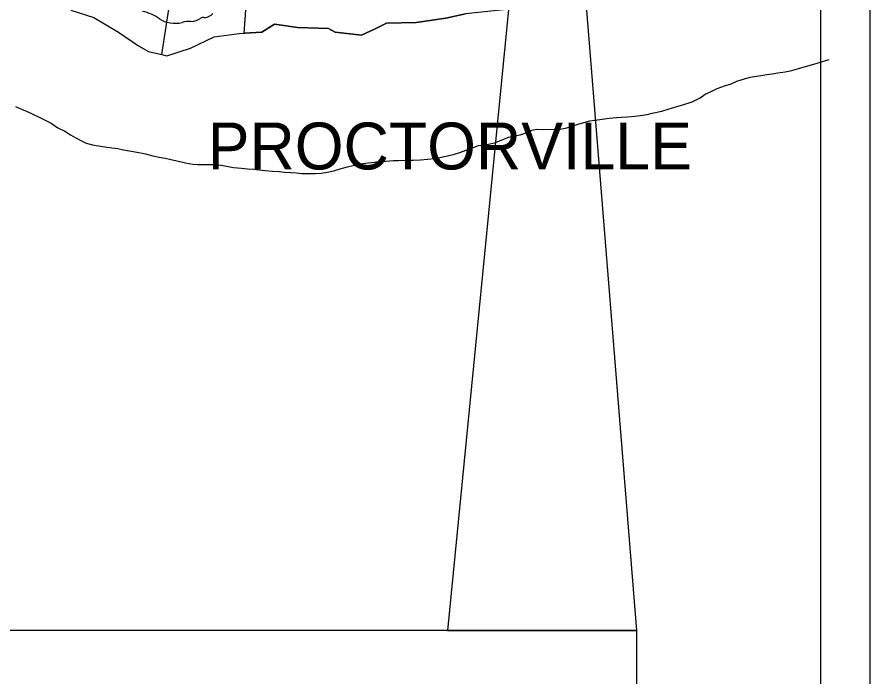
# Model space of a CAD drawing. Extents: x 0 to 34, y 0 to 22.
# Drawn here: x 7.778 to 9.5, y 15.102 to 16.434 of the extents above; entities that cross this region are included whole.
import ezdxf

# ---------------------------------------------------------------- set-up
doc = ezdxf.new("R2010")
doc.units = 0
for name, color, linetype in [('GM_X_Corporation', 7, 'Continuous'), ('GM_X_Corporation_Text', 7, 'Continuous'), ('GM_X_County', 7, 'Continuous'), ('GM_X_Major_River', 7, 'Continuous'), ('GM_X_State_Route', 7, 'Continuous'), ('GM_X_State_Shield', 7, 'Continuous'), ('GM_X_Township', 7, 'Continuous'), ('SH_Data', 7, 'Continuous'), ('SH_Text', 7, 'Continuous')]:
    doc.layers.add(name, color=color, linetype=linetype)

msp = doc.modelspace()

# ---------------------------------------------------------------- linework, layer by layer
at = {"layer": 'GM_X_Corporation'}
msp.add_lwpolyline([(8.236, 16.4015), (8.2709, 16.8756), (8.4678, 16.8002), (8.4665, 16.7841), (8.5125, 16.7805), (8.5113, 16.765), (8.6273, 16.756), (8.6258, 16.7367), (8.9074, 16.7147), (8.8957, 16.4847), (8.8556, 16.4772), (8.7669, 16.4493), (8.683, 16.4407), (8.6432, 16.4316), (8.5837, 16.4231), (8.5237, 16.4215), (8.501, 16.41), (8.4733, 16.3978), (8.4202, 16.4034), (8.4065, 16.411), (8.3439, 16.4128), (8.2972, 16.4195), (8.2722, 16.4039)], close=True, dxfattribs=at)
at = {"layer": 'GM_X_County'}
msp.add_lwpolyline([(7.8859, 16.4481), (7.9326, 16.4334), (7.9823, 16.4038), (8.023, 16.3761), (8.0428, 16.3644), (8.0701, 16.3583), (8.0803, 16.3561), (8.1277, 16.3713), (8.1755, 16.3942), (8.2259, 16.4008), (8.2722, 16.4039), (8.2972, 16.4195), (8.3439, 16.4128), (8.4065, 16.411), (8.4202, 16.4034), (8.4733, 16.3978), (8.501, 16.41), (8.5237, 16.4215), (8.5837, 16.4231), (8.6432, 16.4316), (8.683, 16.4407)], dxfattribs=at)
at = {"layer": 'GM_X_Major_River'}
for points in [[(9.0359, 16.2354), (9.0498, 16.2373), (9.06, 16.2401), (9.0797, 16.2439), (9.0925, 16.2478), (9.1102, 16.2532), (9.1219, 16.2567), (9.1412, 16.2629), (9.157, 16.2709), (9.1672, 16.2786), (9.1808, 16.2847), (9.1913, 16.2897), (9.2083, 16.2962), (9.2181, 16.2985), (9.2313, 16.3043), (9.2464, 16.3093), (9.2581, 16.3124), (9.2797, 16.3159), (9.2917, 16.3179), (9.3027, 16.3191), (9.3137, 16.3214), (9.3288, 16.3234), (9.342, 16.3265), (9.3601, 16.3315), (9.3771, 16.3365), (9.3937, 16.3412), (9.4111, 16.3466), (9.4175, 16.3484)], [(7.7746, 16.2538), (7.7863, 16.2481), (7.7981, 16.2432), (7.8079, 16.2387), (7.8239, 16.2315), (7.8345, 16.2262), (7.8466, 16.2198), (7.8603, 16.2107), (7.8739, 16.2039), (7.8857, 16.1963), (7.8951, 16.1907), (7.9077, 16.1839), (7.9175, 16.1793), (7.93, 16.1759), (7.9459, 16.1733), (7.9592, 16.1715), (7.969, 16.17), (7.9808, 16.1685), (7.9929, 16.1662), (8.005, 16.164), (8.0164, 16.1621), (8.027, 16.1602), (8.0368, 16.158), (8.0516, 16.1539), (8.0648, 16.1512), (8.0766, 16.149), (8.0883, 16.1464), (8.1039, 16.143), (8.1179, 16.1396), (8.1326, 16.137), (8.1425, 16.1366), (8.1546, 16.1363), (8.166, 16.1363), (8.1796, 16.1363), (8.1936, 16.1341), (8.2038, 16.1322), (8.2148, 16.1303), (8.2311, 16.1289), (8.2432, 16.1278), (8.2557, 16.1267), (8.2663, 16.1255), (8.2784, 16.1241), (8.2932, 16.123), (8.3068, 16.1219), (8.3178, 16.1211), (8.3307, 16.12), (8.342, 16.1193), (8.353, 16.1182), (8.3655, 16.1182), (8.3799, 16.1182), (8.3916, 16.1187), (8.4048, 16.121), (8.4196, 16.124), (8.4321, 16.1283), (8.4449, 16.1313), (8.4593, 16.1348), (8.4756, 16.1382), (8.4934, 16.1402), (8.5089, 16.1421), (8.5225, 16.1429), (8.5369, 16.1441), (8.5471, 16.1445), (8.5611, 16.1449), (8.5778, 16.145), (8.5925, 16.1458), (8.6065, 16.1469), (8.6209, 16.1485), (8.6345, 16.1512), (8.6493, 16.1543), (8.6591, 16.1566), (8.672, 16.1604)], [(8.8746, 16.2076), (8.8878, 16.2107), (8.8999, 16.2146), (8.9105, 16.2177), (8.9222, 16.2212), (8.9346, 16.2243), (8.9445, 16.2262), (8.9592, 16.2282), (8.9735, 16.2298), (8.9883, 16.2314), (8.9992, 16.2318), (9.0113, 16.2326), (9.0249, 16.2342), (9.0359, 16.2354)], [(8.672, 16.1604), (8.6844, 16.165), (8.6962, 16.1692), (8.7094, 16.1749), (8.7238, 16.1761), (8.7419, 16.18), (8.754, 16.1849), (8.7688, 16.1907), (8.7805, 16.1941), (8.7937, 16.1961), (8.8055, 16.2003), (8.8175, 16.2056), (8.8274, 16.2076), (8.8395, 16.2072), (8.8746, 16.2076)]]:
    msp.add_lwpolyline(points, dxfattribs=at)
at = {"layer": 'GM_X_State_Route'}
msp.add_lwpolyline([(8.0701, 16.3583), (8.0873, 16.4725), (8.1191, 16.6946)], dxfattribs=at)
at = {"layer": 'GM_X_State_Shield'}
for centre, major_axis, start_param, end_param in [((8.0114, 16.3842), (0.079, 0), 0.823519, 1.323587), ((8.1294, 16.4466), (0.0267, 0), 4.691044, 5.507374), ((8.1536, 16.4272), (0.00752, 0), 1.147584, 2.315152), ((8.1503, 16.4547), (0.0282, 0), 4.937069, 5.64225), ((8.0968, 16.4615), (0.0501, 0), 4.026481, 4.996735), ((8.1257, 16.3923), (0.0412, 0), 1.495662, 1.94098)]:
    msp.add_ellipse(centre, major_axis=major_axis, ratio=0.8, start_param=start_param, end_param=end_param, dxfattribs=at)
at = {"layer": 'GM_X_Township'}
msp.add_lwpolyline([(7.8859, 16.4481), (7.9326, 16.4334), (7.9823, 16.4038), (8.023, 16.3761), (8.0428, 16.3644), (8.0701, 16.3583), (8.0803, 16.3561), (8.1277, 16.3713), (8.1755, 16.3942), (8.2259, 16.4008), (8.2722, 16.4039), (8.2972, 16.4195), (8.3439, 16.4128), (8.4065, 16.411), (8.4202, 16.4034), (8.4733, 16.3978), (8.501, 16.41), (8.5237, 16.4215), (8.5837, 16.4231), (8.6432, 16.4316), (8.683, 16.4407)], dxfattribs=at)
at = {"layer": 'SH_Data'}
for p, q in [((9.5, 21), (9.5, 14)), ((9.4, 20.9), (9.4, 14.1))]:
    msp.add_line(p, q, dxfattribs=at)
at = {"layer": 'SH_Text'}
for points in [[(9.029, 15.1955), (8.857, 17.3337), (8.6468, 15.1955)], [(9.029, 15.1955), (7.186, 15.1955), (7.186, 14.3684), (9.029, 14.3684)]]:
    msp.add_lwpolyline(points, close=True, dxfattribs=at)

# ---------------------------------------------------------------- texts
at = {"layer": 'GM_X_Corporation_Text'}
msp.add_text('PROCTORVILLE', height=0.094697, rotation=0, dxfattribs=at).set_placement((8.1626, 16.1263))

doc.saveas('drawing.dxf')
